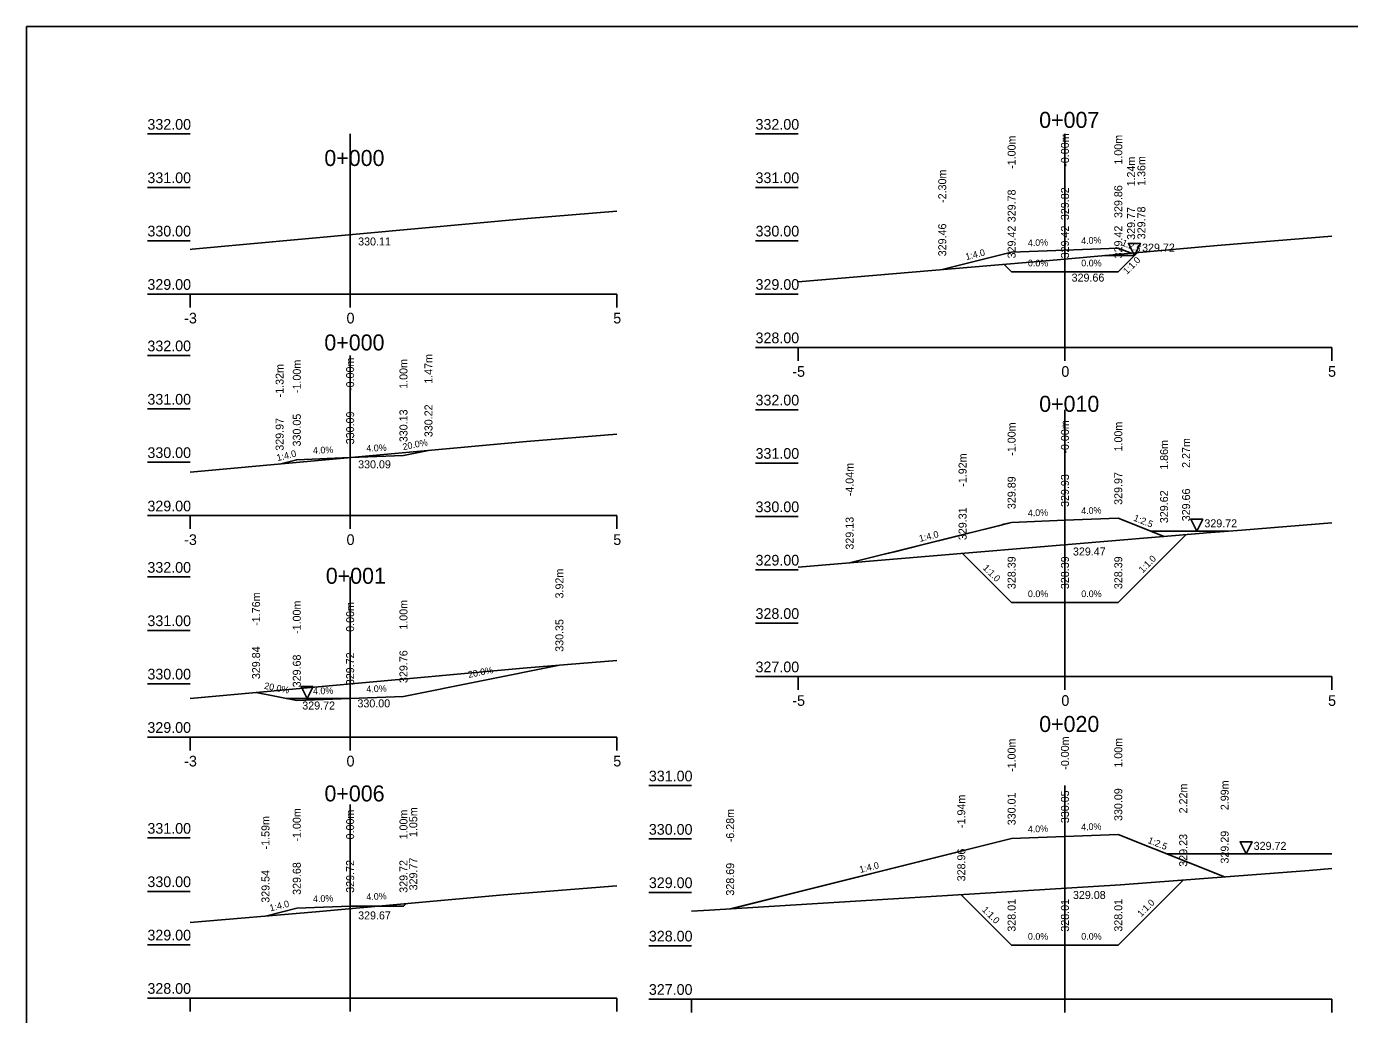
# Model space of a CAD drawing. Extents: x -560266.4 to -560224.4, y -1163068.4 to -1163038.7.
# Drawn here: x -560266.44 to -560241.64, y -1163057.22 to -1163038.7 of the extents above; entities that cross this region are included whole.
import ezdxf

# ---------------------------------------------------------------- set-up
doc = ezdxf.new("R2010")
doc.units = 0
for name, color, linetype in [('16', 7, 'Continuous'), ('21', 7, 'Continuous'), ('28', 7, 'Continuous'), ('59', 7, 'Continuous'), ('Body pricny rez', 7, 'Continuous'), ('Popis pricneho profilu', 7, 'Continuous')]:
    doc.layers.add(name, color=color, linetype=linetype)

msp = doc.modelspace()

# ---------------------------------------------------------------- linework, layer by layer
for p, q in [((-560224.444, -1163038.703), (-560266.444, -1163038.703)), ((-560266.444, -1163038.703), (-560266.444, -1163068.403))]:
    msp.add_line(p, q)
for points in [[(-560263.377, -1163042.879), (-560263.341, -1163042.876), (-560257.053, -1163042.303), (-560255.377, -1163042.165)], [(-560251.977, -1163043.489), (-560247.338, -1163043.094), (-560244.125, -1163042.805), (-560241.977, -1163042.634)], [(-560247.977, -1163042.934), (-560249.277, -1163043.259)], [(-560248.115, -1163043.16), (-560247.977, -1163043.298), (-560247.488, -1163043.298), (-560246.977, -1163043.298), (-560246.488, -1163043.298), (-560245.977, -1163043.298), (-560245.955, -1163043.276), (-560245.618, -1163042.94)], [(-560246.977, -1163042.894), (-560247.977, -1163042.934)], [(-560246.977, -1163042.894), (-560245.977, -1163042.854)], [(-560245.977, -1163042.854), (-560245.737, -1163042.95)], [(-560245.977, -1163043.298), (-560245.618, -1163042.94)], [(-560246.227, -1163042.994), (-560245.673, -1163042.994)], [(-560246.977, -1163043.298), (-560247.977, -1163043.298)], [(-560246.977, -1163043.298), (-560245.977, -1163043.298)], [(-560263.377, -1163047.055), (-560257.071, -1163046.481), (-560255.377, -1163046.342)], [(-560261.699, -1163046.902), (-560261.377, -1163046.822), (-560260.377, -1163046.782), (-560259.377, -1163046.742), (-560258.908, -1163046.648)], [(-560259.377, -1163046.742), (-560258.908, -1163046.648)], [(-560260.377, -1163046.782), (-560261.377, -1163046.822)], [(-560260.377, -1163046.782), (-560259.377, -1163046.742)], [(-560251.014, -1163048.755), (-560250.365, -1163048.593), (-560250.169, -1163048.544), (-560249.577, -1163048.396), (-560249.146, -1163048.288), (-560248.828, -1163048.209), (-560248.175, -1163048.045), (-560248.12, -1163048.031), (-560247.977, -1163047.996), (-560246.977, -1163047.956), (-560245.977, -1163047.916), (-560245.119, -1163048.259)], [(-560246.977, -1163047.956), (-560245.977, -1163047.916)], [(-560245.977, -1163047.916), (-560245.119, -1163048.259)], [(-560251.977, -1163048.836), (-560244.387, -1163048.197), (-560244.325, -1163048.193), (-560243.661, -1163048.14), (-560241.977, -1163048.004)], [(-560247.977, -1163047.996), (-560251.014, -1163048.755)], [(-560246.977, -1163047.956), (-560247.977, -1163047.996)], [(-560245.365, -1163048.16), (-560243.921, -1163048.16)], [(-560248.896, -1163048.577), (-560247.977, -1163049.495), (-560246.977, -1163049.495), (-560245.977, -1163049.495), (-560244.706, -1163048.224)], [(-560245.977, -1163049.495), (-560244.706, -1163048.224)], [(-560247.977, -1163049.495), (-560248.896, -1163048.577)], [(-560246.977, -1163049.495), (-560247.977, -1163049.495)], [(-560246.977, -1163049.495), (-560245.977, -1163049.495)], [(-560263.377, -1163051.295), (-560257.131, -1163050.726), (-560256.302, -1163050.658), (-560255.377, -1163050.583)], [(-560259.377, -1163051.255), (-560256.454, -1163050.67)], [(-560261.377, -1163051.335), (-560262.14, -1163051.182)], [(-560261.577, -1163051.295), (-560260.38, -1163051.295)], [(-560260.377, -1163051.295), (-560261.377, -1163051.335)], [(-560260.377, -1163051.295), (-560259.377, -1163051.255)], [(-560253.253, -1163055.238), (-560253.222, -1163055.231), (-560253.212, -1163055.228), (-560247.977, -1163053.92), (-560246.977, -1163053.88), (-560245.977, -1163053.84), (-560243.983, -1163054.637)], [(-560246.977, -1163053.88), (-560247.977, -1163053.92)], [(-560246.977, -1163053.88), (-560245.977, -1163053.84)], [(-560245.977, -1163053.84), (-560243.983, -1163054.637)], [(-560247.977, -1163053.92), (-560253.253, -1163055.238)], [(-560245.066, -1163054.204), (-560241.977, -1163054.204)], [(-560253.977, -1163055.282), (-560253.639, -1163055.262), (-560245.934, -1163054.786), (-560242.401, -1163054.516), (-560241.977, -1163054.483)], [(-560263.377, -1163055.492), (-560261.017, -1163055.291), (-560257.502, -1163054.975), (-560255.377, -1163054.806)], [(-560248.92, -1163054.971), (-560247.977, -1163055.914), (-560246.977, -1163055.914), (-560245.977, -1163055.914), (-560244.76, -1163054.697)], [(-560245.977, -1163055.914), (-560244.76, -1163054.697)], [(-560247.977, -1163055.914), (-560248.92, -1163054.971)], [(-560261.377, -1163055.225), (-560261.964, -1163055.372)], [(-560260.377, -1163055.185), (-560261.377, -1163055.225)], [(-560260.377, -1163055.185), (-560259.377, -1163055.185)], [(-560259.377, -1163055.185), (-560259.332, -1163055.14)], [(-560246.977, -1163055.914), (-560247.977, -1163055.914)], [(-560246.977, -1163055.914), (-560245.977, -1163055.914)]]:
    msp.add_lwpolyline(points)
for points in [[(-560245.673, -1163042.994), (-560245.786, -1163042.769), (-560245.561, -1163042.769)], [(-560244.505, -1163048.16), (-560244.618, -1163047.935), (-560244.393, -1163047.935)], [(-560261.185, -1163051.295), (-560261.297, -1163051.07), (-560261.072, -1163051.07)], [(-560243.582, -1163054.204), (-560243.694, -1163053.979), (-560243.469, -1163053.979)]]:
    msp.add_lwpolyline(points, close=True)
at = {"layer": '16'}
for p, q in [((-560263.377, -1163043.717), (-560255.377, -1163043.717)), ((-560251.977, -1163044.717), (-560241.977, -1163044.717)), ((-560263.377, -1163047.868), (-560255.377, -1163047.868)), ((-560251.977, -1163050.883), (-560241.977, -1163050.883)), ((-560263.377, -1163052.018), (-560255.377, -1163052.018)), ((-560263.377, -1163056.908), (-560255.377, -1163056.908)), ((-560253.977, -1163056.927), (-560241.977, -1163056.927))]:
    msp.add_line(p, q, dxfattribs=at)
at = {"layer": '21'}
for p, q in [((-560264.177, -1163040.717), (-560263.377, -1163040.717)), ((-560252.777, -1163040.717), (-560251.977, -1163040.717)), ((-560264.177, -1163041.717), (-560263.377, -1163041.717)), ((-560252.777, -1163041.717), (-560251.977, -1163041.717)), ((-560264.177, -1163042.717), (-560263.377, -1163042.717)), ((-560252.777, -1163042.717), (-560251.977, -1163042.717)), ((-560264.177, -1163043.717), (-560263.377, -1163043.717)), ((-560252.777, -1163043.717), (-560251.977, -1163043.717)), ((-560252.777, -1163044.717), (-560251.977, -1163044.717)), ((-560264.177, -1163044.868), (-560263.377, -1163044.868)), ((-560264.177, -1163045.868), (-560263.377, -1163045.868)), ((-560252.777, -1163045.883), (-560251.977, -1163045.883)), ((-560264.177, -1163046.868), (-560263.377, -1163046.868)), ((-560252.777, -1163046.883), (-560251.977, -1163046.883)), ((-560264.177, -1163047.868), (-560263.377, -1163047.868)), ((-560252.777, -1163047.883), (-560251.977, -1163047.883)), ((-560252.777, -1163048.883), (-560251.977, -1163048.883)), ((-560264.177, -1163049.018), (-560263.377, -1163049.018)), ((-560252.777, -1163049.883), (-560251.977, -1163049.883)), ((-560264.177, -1163050.018), (-560263.377, -1163050.018)), ((-560252.777, -1163050.883), (-560251.977, -1163050.883)), ((-560264.177, -1163051.018), (-560263.377, -1163051.018)), ((-560264.177, -1163052.018), (-560263.377, -1163052.018)), ((-560254.777, -1163052.927), (-560253.977, -1163052.927)), ((-560264.177, -1163053.908), (-560263.377, -1163053.908)), ((-560254.777, -1163053.927), (-560253.977, -1163053.927)), ((-560264.177, -1163054.908), (-560263.377, -1163054.908)), ((-560254.777, -1163054.927), (-560253.977, -1163054.927)), ((-560264.177, -1163055.908), (-560263.377, -1163055.908)), ((-560254.777, -1163055.927), (-560253.977, -1163055.927)), ((-560264.177, -1163056.908), (-560263.377, -1163056.908)), ((-560254.777, -1163056.927), (-560253.977, -1163056.927))]:
    msp.add_line(p, q, dxfattribs=at)
at = {"layer": '28'}
for p, q in [((-560260.377, -1163040.717), (-560260.377, -1163043.717)), ((-560246.977, -1163040.717), (-560246.977, -1163044.717)), ((-560260.377, -1163044.868), (-560260.377, -1163047.868)), ((-560246.977, -1163045.883), (-560246.977, -1163050.883)), ((-560260.377, -1163049.018), (-560260.377, -1163052.018)), ((-560246.977, -1163052.927), (-560246.977, -1163056.927)), ((-560260.377, -1163053.283), (-560260.377, -1163056.908))]:
    msp.add_line(p, q, dxfattribs=at)
at = {"layer": '59'}
for p, q in [((-560263.377, -1163043.967), (-560263.377, -1163043.717)), ((-560260.377, -1163043.967), (-560260.377, -1163043.717)), ((-560255.377, -1163043.967), (-560255.377, -1163043.717)), ((-560251.977, -1163044.967), (-560251.977, -1163044.717)), ((-560246.977, -1163044.967), (-560246.977, -1163044.717)), ((-560241.977, -1163044.967), (-560241.977, -1163044.717)), ((-560263.377, -1163048.118), (-560263.377, -1163047.868)), ((-560260.377, -1163048.118), (-560260.377, -1163047.868)), ((-560255.377, -1163048.118), (-560255.377, -1163047.868)), ((-560251.977, -1163051.133), (-560251.977, -1163050.883)), ((-560246.977, -1163051.133), (-560246.977, -1163050.883)), ((-560241.977, -1163051.133), (-560241.977, -1163050.883)), ((-560263.377, -1163052.268), (-560263.377, -1163052.018)), ((-560260.377, -1163052.268), (-560260.377, -1163052.018)), ((-560255.377, -1163052.268), (-560255.377, -1163052.018)), ((-560263.377, -1163057.158), (-560263.377, -1163056.908)), ((-560260.377, -1163057.158), (-560260.377, -1163056.908)), ((-560255.377, -1163057.158), (-560255.377, -1163056.908)), ((-560253.977, -1163057.177), (-560253.977, -1163056.927)), ((-560246.977, -1163057.177), (-560246.977, -1163056.927)), ((-560241.977, -1163057.177), (-560241.977, -1163056.927))]:
    msp.add_line(p, q, dxfattribs=at)

# ---------------------------------------------------------------- texts
for s, height, p in [('0+007', 0.3, (-560247.46, -1163040.603)), ('0+000', 0.3, (-560260.86, -1163041.317)), ('329.72', 0.15, (-560245.531, -1163042.921)), ('0+000', 0.3, (-560260.86, -1163044.773)), ('0+010', 0.3, (-560247.46, -1163045.923)), ('329.72', 0.15, (-560244.363, -1163048.087)), ('0+001', 0.3, (-560260.833, -1163049.145)), ('329.72', 0.15, (-560261.274, -1163051.501)), ('0+020', 0.3, (-560247.46, -1163051.922)), ('0+006', 0.3, (-560260.858, -1163053.223)), ('329.72', 0.15, (-560243.439, -1163054.131))]:
    msp.add_text(s, height=height).set_placement(p)
for s, rotation, p in [('1:2.5', 338.1986, (-560245.925, -1163042.801)), ('1:4.0', 14.0362, (-560248.826, -1163043.082)), ('1:1.0', 45, (-560245.813, -1163043.355)), ('1:4.0', 14.0362, (-560261.737, -1163046.848)), ('1:2.5', 338.1986, (-560245.702, -1163047.958)), ('1:4.0', 14.0362, (-560249.695, -1163048.361)), ('1:1.0', 45, (-560245.52, -1163048.95)), ('1:1.0', 315, (-560248.526, -1163048.857)), ('1:2.5', 338.1986, (-560245.434, -1163053.999)), ('1:4.0', 14.0362, (-560250.814, -1163054.564)), ('1:4.0', 14.0362, (-560261.87, -1163055.284)), ('1:1.0', 45, (-560245.547, -1163055.395)), ('1:1.0', 315, (-560248.539, -1163055.264))]:
    msp.add_text(s, height=0.125, rotation=rotation).set_placement(p)
at = {"layer": '16'}
for s, rotation, p in [('4.0%', 2.2906, (-560247.671, -1163042.822)), ('4.0%', 2.2906, (-560246.671, -1163042.782)), ('0.0%', 0, (-560247.671, -1163043.198)), ('20.0%', 11.3099, (-560259.38, -1163046.643)), ('4.0%', 2.2906, (-560261.071, -1163046.71)), ('4.0%', 2.2906, (-560260.071, -1163046.67)), ('4.0%', 2.2906, (-560247.671, -1163047.883)), ('4.0%', 2.2906, (-560246.671, -1163047.843)), ('20.0%', 11.3099, (-560258.153, -1163050.91)), ('20.0%', 348.6901, (-560261.996, -1163051.111)), ('4.0%', 2.2906, (-560261.071, -1163051.222)), ('4.0%', 2.2906, (-560260.071, -1163051.182)), ('4.0%', 2.2906, (-560246.671, -1163053.767)), ('4.0%', 2.2906, (-560247.671, -1163053.807)), ('4.0%', 2.2906, (-560261.071, -1163055.113)), ('4.0%', 2.2906, (-560260.071, -1163055.073))]:
    msp.add_text(s, height=0.125, rotation=rotation, dxfattribs=at).set_placement(p)
for p in [(-560246.671, -1163043.198), (-560247.671, -1163049.395), (-560246.671, -1163049.395), (-560247.671, -1163055.814), (-560246.671, -1163055.814)]:
    msp.add_text('0.0%', height=0.125, dxfattribs=at).set_placement(p)
at = {"layer": '21'}
for s, p in [('332.00', (-560264.177, -1163040.637)), ('332.00', (-560252.777, -1163040.637)), ('331.00', (-560264.177, -1163041.637)), ('331.00', (-560252.777, -1163041.637)), ('330.00', (-560264.177, -1163042.637)), ('330.00', (-560252.777, -1163042.637)), ('329.00', (-560264.177, -1163043.637)), ('329.00', (-560252.777, -1163043.637)), ('-3', (-560263.488, -1163044.267)), ('0', (-560260.444, -1163044.267)), ('5', (-560255.444, -1163044.267)), ('328.00', (-560252.777, -1163044.637)), ('332.00', (-560264.177, -1163044.788)), ('-5', (-560252.088, -1163045.267)), ('0', (-560247.044, -1163045.267)), ('5', (-560242.044, -1163045.267)), ('331.00', (-560264.177, -1163045.788)), ('332.00', (-560252.777, -1163045.803)), ('330.00', (-560264.177, -1163046.788)), ('331.00', (-560252.777, -1163046.803)), ('329.00', (-560264.177, -1163047.788)), ('330.00', (-560252.777, -1163047.803)), ('-3', (-560263.488, -1163048.418)), ('0', (-560260.444, -1163048.418)), ('5', (-560255.444, -1163048.418)), ('329.00', (-560252.777, -1163048.803)), ('332.00', (-560264.177, -1163048.938)), ('328.00', (-560252.777, -1163049.803)), ('331.00', (-560264.177, -1163049.938)), ('327.00', (-560252.777, -1163050.803)), ('330.00', (-560264.177, -1163050.938)), ('-5', (-560252.088, -1163051.433)), ('0', (-560247.044, -1163051.433)), ('5', (-560242.044, -1163051.433)), ('329.00', (-560264.177, -1163051.938)), ('-3', (-560263.488, -1163052.568)), ('0', (-560260.444, -1163052.568)), ('5', (-560255.444, -1163052.568)), ('331.00', (-560254.777, -1163052.847)), ('331.00', (-560264.177, -1163053.828)), ('330.00', (-560254.777, -1163053.847)), ('330.00', (-560264.177, -1163054.828)), ('329.00', (-560254.777, -1163054.847)), ('329.00', (-560264.177, -1163055.828)), ('328.00', (-560254.777, -1163055.847)), ('328.00', (-560264.177, -1163056.828)), ('327.00', (-560254.777, -1163056.847))]:
    msp.add_text(s, height=0.2, dxfattribs=at).set_placement(p)
at = {"layer": '59'}
for s, p in [('330.11', (-560260.227, -1163042.806)), ('329.66', (-560246.852, -1163043.483)), ('330.09', (-560260.227, -1163046.982)), ('329.47', (-560246.827, -1163048.615)), ('330.00', (-560260.24, -1163051.461)), ('329.08', (-560246.827, -1163055.051)), ('329.67', (-560260.227, -1163055.434))]:
    msp.add_text(s, height=0.15, dxfattribs=at).set_placement(p)
at = {"layer": 'Body pricny rez'}
for p in [(-560247.978, -1163042.935), (-560246.978, -1163042.895), (-560245.978, -1163042.855), (-560245.737, -1163042.951), (-560245.619, -1163042.94), (-560249.277, -1163043.26), (-560247.978, -1163043.299), (-560246.978, -1163043.299), (-560245.978, -1163043.299), (-560258.908, -1163046.649), (-560261.699, -1163046.903), (-560261.378, -1163046.822), (-560260.378, -1163046.782), (-560259.378, -1163046.742), (-560245.978, -1163047.916), (-560247.978, -1163047.996), (-560246.978, -1163047.956), (-560245.12, -1163048.259), (-560244.707, -1163048.225), (-560248.896, -1163048.577), (-560251.014, -1163048.755), (-560247.978, -1163049.495), (-560246.978, -1163049.495), (-560245.978, -1163049.495), (-560256.455, -1163050.671), (-560262.14, -1163051.183), (-560261.378, -1163051.335), (-560260.378, -1163051.295), (-560259.378, -1163051.255), (-560246.978, -1163053.88), (-560245.978, -1163053.84), (-560247.978, -1163053.92), (-560243.984, -1163054.638), (-560244.76, -1163054.697), (-560248.92, -1163054.971), (-560261.965, -1163055.372), (-560261.378, -1163055.226), (-560260.378, -1163055.186), (-560260.378, -1163055.186), (-560259.378, -1163055.186), (-560259.332, -1163055.14), (-560253.253, -1163055.239), (-560247.978, -1163055.914), (-560246.978, -1163055.914), (-560245.978, -1163055.914)]:
    msp.add_text('+', height=0.001, dxfattribs=at).set_placement(p)
at = {"layer": 'Popis pricneho profilu'}
for s, p in [('-0.00m', (-560246.902, -1163041.331)), ('1.00m', (-560245.902, -1163041.291)), ('-1.00m', (-560247.902, -1163041.371)), ('1.24m', (-560245.662, -1163041.7)), ('1.36m', (-560245.469, -1163041.69)), ('-2.30m', (-560249.202, -1163042.009)), ('329.82', (-560246.902, -1163042.331)), ('329.86', (-560245.902, -1163042.291)), ('329.78', (-560247.902, -1163042.371)), ('329.77', (-560245.662, -1163042.7)), ('329.78', (-560245.469, -1163042.69)), ('329.46', (-560249.202, -1163043.009)), ('329.42', (-560247.902, -1163043.048)), ('329.42', (-560246.902, -1163043.048)), ('329.42', (-560245.902, -1163043.048)), ('-1.00m', (-560261.302, -1163045.572)), ('-0.00m', (-560260.302, -1163045.532)), ('1.00m', (-560259.302, -1163045.492)), ('1.47m', (-560258.833, -1163045.398)), ('-1.32m', (-560261.624, -1163045.652)), ('330.09', (-560260.302, -1163046.532)), ('330.13', (-560259.302, -1163046.492)), ('330.22', (-560258.833, -1163046.398)), ('329.97', (-560261.624, -1163046.652)), ('330.05', (-560261.302, -1163046.572)), ('-1.00m', (-560247.902, -1163046.746)), ('-0.00m', (-560246.902, -1163046.706)), ('1.00m', (-560245.902, -1163046.666)), ('2.27m', (-560244.631, -1163046.974)), ('1.86m', (-560245.044, -1163047.009)), ('-4.04m', (-560250.939, -1163047.505)), ('-1.92m', (-560248.821, -1163047.327)), ('329.89', (-560247.902, -1163047.746)), ('329.93', (-560246.902, -1163047.706)), ('329.97', (-560245.902, -1163047.666)), ('329.62', (-560245.044, -1163048.009)), ('329.66', (-560244.631, -1163047.974)), ('329.13', (-560250.939, -1163048.505)), ('329.31', (-560248.821, -1163048.327)), ('328.39', (-560247.902, -1163049.245)), ('328.39', (-560246.902, -1163049.245)), ('328.39', (-560245.902, -1163049.245)), ('3.92m', (-560256.379, -1163049.42)), ('-1.76m', (-560262.065, -1163049.932)), ('-1.00m', (-560261.302, -1163050.085)), ('0.00m', (-560260.302, -1163050.045)), ('1.00m', (-560259.302, -1163050.005)), ('330.35', (-560256.379, -1163050.42)), ('329.84', (-560262.065, -1163050.932)), ('329.76', (-560259.302, -1163051.005)), ('329.68', (-560261.302, -1163051.085)), ('329.72', (-560260.302, -1163051.045)), ('-1.00m', (-560247.902, -1163052.67)), ('-0.00m', (-560246.902, -1163052.63)), ('1.00m', (-560245.902, -1163052.59)), ('2.22m', (-560244.685, -1163053.447)), ('2.99m', (-560243.908, -1163053.387)), ('-1.94m', (-560248.845, -1163053.721)), ('330.01', (-560247.902, -1163053.67)), ('330.05', (-560246.902, -1163053.63)), ('330.09', (-560245.902, -1163053.59)), ('-1.00m', (-560261.302, -1163053.975)), ('0.00m', (-560260.302, -1163053.935)), ('1.00m', (-560259.302, -1163053.935)), ('1.05m', (-560259.118, -1163053.89)), ('-6.28m', (-560253.178, -1163053.988)), ('-1.59m', (-560261.889, -1163054.122)), ('329.23', (-560244.685, -1163054.447)), ('329.29', (-560243.908, -1163054.387)), ('328.96', (-560248.845, -1163054.721)), ('329.68', (-560261.302, -1163054.975)), ('329.72', (-560260.302, -1163054.935)), ('329.72', (-560259.302, -1163054.935)), ('329.77', (-560259.118, -1163054.89)), ('328.69', (-560253.178, -1163054.988)), ('329.54', (-560261.889, -1163055.122)), ('328.01', (-560247.902, -1163055.664)), ('328.01', (-560246.902, -1163055.664)), ('328.01', (-560245.902, -1163055.664))]:
    msp.add_text(s, height=0.15, rotation=90, dxfattribs=at).set_placement(p)

doc.saveas('drawing.dxf')
